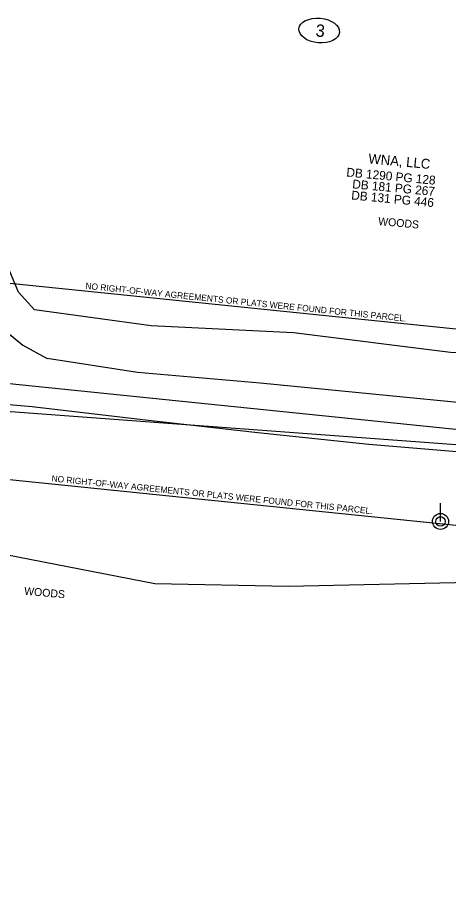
# Model space of a CAD drawing. Extents: x 2060057 to 2062431, y 911685 to 913703.
# Drawn here: x 2061420.6 to 2061552.2, y 912533.1 to 912797.2 of the extents above; entities that cross this region are included whole.
import ezdxf

# ---------------------------------------------------------------- set-up
doc = ezdxf.new("R2010")
doc.units = 0
for name, color, linetype in [('Exist Horizontal Alignment', 7, 'Continuous'), ('Exist Horizontal Baseline Alignment', 7, 'Continuous'), ('Exist Property Deed Book Text', 7, 'Continuous'), ('Exist Property Owner Number Topo CELL', 7, 'Continuous'), ('Exist Property Owner Text', 7, 'Continuous'), ('Exist Right of Way Line', 7, 'Continuous'), ('Exist Right of Way Line Text', 7, 'Continuous'), ('Exist Roads Soil', 7, 'Continuous'), ('Exist Utilities Power Pole CELL', 7, 'Continuous'), ('Exist Vegetation Woods Line', 7, 'Continuous'), ('Exist Vegetation Woods Line Text', 7, 'Continuous')]:
    doc.layers.add(name, color=color, linetype=linetype)

# ---------------------------------------------------------------- blocks, each defined once
blk = doc.blocks.new('EXIST UTILITIES POWER POLE')
at = {"layer": 'Exist Utilities Power Pole CELL'}
for q in [(0, 0.1125), (0, 0)]:
    blk.add_line((0, 0), q, dxfattribs=at)
blk.add_circle((0, 0), 0.049, dxfattribs=at)

msp = doc.modelspace()

# ---------------------------------------------------------------- linework, layer by layer
at = {"layer": 'Exist Horizontal Alignment'}
msp.add_lwpolyline([(2061408.16, 912686.46), (2061606.07, 912666.22)], dxfattribs=at)
at = {"layer": 'Exist Horizontal Baseline Alignment'}
msp.add_lwpolyline([(2060519.43, 912752.09), (2061230.37, 912690.89), (2061909.97, 912640.52)], dxfattribs=at)
at = {"layer": 'Exist Property Owner Number Topo CELL'}
msp.add_ellipse((2061512.72, 912793.19), major_axis=(6.2, -0.55), ratio=0.60241, dxfattribs=at)
at = {"layer": 'Exist Right of Way Line'}
for points in [[(2061411.27, 912716.85), (2061609.17, 912696.6)], [(2061405.19, 912657.45), (2061603.1, 912637.2)]]:
    msp.add_lwpolyline(points, dxfattribs=at)
at = {"layer": 'Exist Roads Soil'}
for p, q in [((2061391.87, 912681.43), (2061425.16, 912678.44)), ((2061425.16, 912678.44), (2061458.76, 912674.47)), ((2061458.76, 912674.47), (2061493.97, 912670.51)), ((2061493.97, 912670.51), (2061527.89, 912666.97)), ((2061527.89, 912666.97), (2061560.93, 912664.14))]:
    msp.add_line(p, q, dxfattribs=at)
for points in [[(2061403.48, 912721.06), (2061405.78, 912716.63), (2061412.47, 912706.51), (2061417.65, 912701), (2061422.25, 912697.14), (2061429.74, 912693.06)], [(2061457.3, 912688.8), (2061429.74, 912693.06)], [(2061785.39, 912666.61), (2061760.79, 912666.33), (2061729.65, 912665.79), (2061695.77, 912667.16), (2061662.77, 912669.53), (2061629.67, 912672.23), (2061595.6, 912675.15), (2061562.27, 912678.91), (2061528.97, 912682.23), (2061494.66, 912685.54), (2061457.3, 912688.8)]]:
    msp.add_lwpolyline(points, dxfattribs=at)
at = {"layer": 'Exist Utilities Power Pole CELL'}
for q in [(2061549.73, 912648.98), (2061549.73, 912643.36)]:
    msp.add_line((2061549.73, 912643.36), q, dxfattribs=at)
msp.add_circle((2061549.73, 912643.36), 2.45, dxfattribs=at)
at = {"layer": 'Exist Vegetation Woods Line'}
for points in [[(2061778.62, 912688.7), (2061725.32, 912686.49), (2061660.42, 912690.37), (2061599.1, 912694.44), (2061552.76, 912694.9), (2061504.88, 912700.89), (2061461.45, 912703.12), (2061425.88, 912707.99), (2061421.01, 912713.38), (2061414.09, 912729.67)], [(2061328.45, 912524.64), (2061334.96, 912543.86), (2061338.16, 912555.62), (2061335.77, 912563.65), (2061335.32, 912575.51), (2061329.09, 912578.46), (2061326.65, 912579.8), (2061324.22, 912588.06), (2061323.27, 912593.05), (2061324.97, 912602.58), (2061324.93, 912612.64), (2061321.25, 912622.79), (2061313.21, 912633.86), (2061306.5, 912642.57), (2061311.89, 912646.74), (2061336.29, 912643.55), (2061405.5, 912635.51), (2061462.58, 912624.41), (2061503.33, 912623.58), (2061558.83, 912624.85)]]:
    msp.add_lwpolyline(points, dxfattribs=at)

# ---------------------------------------------------------------- block references
at = {"layer": 'Exist Utilities Power Pole CELL', "xscale": 30, "yscale": 30}
msp.add_blockref('EXIST UTILITIES POWER POLE', (2061549.73, 912643.36), dxfattribs=at)

# ---------------------------------------------------------------- texts
at = {"layer": 'Exist Property Deed Book Text'}
for s, p in [('DB 1290 PG 128', (2061520.92, 912748.66)), ('DB 181 PG 267', (2061522.72, 912745.06)), ('DB 131 PG 446', (2061522.41, 912741.65))]:
    msp.add_text(s, height=2.7, rotation=354.6833, dxfattribs=at).set_placement(p)
at = {"layer": 'Exist Property Owner Number Topo CELL'}
msp.add_text('3', height=3.75, rotation=354.9115, dxfattribs=at).set_placement((2061511.5, 912791.42))
at = {"layer": 'Exist Property Owner Text'}
msp.add_text('WNA, LLC', height=3, rotation=354.6833, dxfattribs=at).set_placement((2061527.61, 912752.68))
at = {"layer": 'Exist Right of Way Line Text'}
for p in [(2061441.32, 912714.36), (2061430.98, 912655.6)]:
    msp.add_text('NO RIGHT-OF-WAY AGREEMENTS OR PLATS WERE FOUND FOR THIS PARCEL.', height=1.92, rotation=354.1591, dxfattribs=at).set_placement(p)
at = {"layer": 'Exist Vegetation Woods Line Text'}
for p in [(2061530.64, 912733.86), (2061422.62, 912621)]:
    msp.add_text('WOODS', height=2.4, rotation=354.9115, dxfattribs=at).set_placement(p)

doc.saveas('drawing.dxf')
